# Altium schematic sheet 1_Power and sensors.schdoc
size 307 x 218 mm; Symbol: Drawing-Symbol_A4; Device: Drawing-Symbol_A4; @Project Name: Avian; @Page Count: 2; @Update Date: 2026-02-02; @Create Date: 2026-01-29; @Schematic Name: Avian_1; @Page No: 1; @Page Name: Power and sensors; Company: EasyEDA.com; Version: V1.0; Page Size: A4; @Create Time: 21:50:30; @Update Time: 22:16:31; Width: 1170; Height: 825; Region Start: 1; X Region Count: 6; Y Region Count: 4; Blade Width: 10; Title Block Position: 3; @Board Name: Avian_1
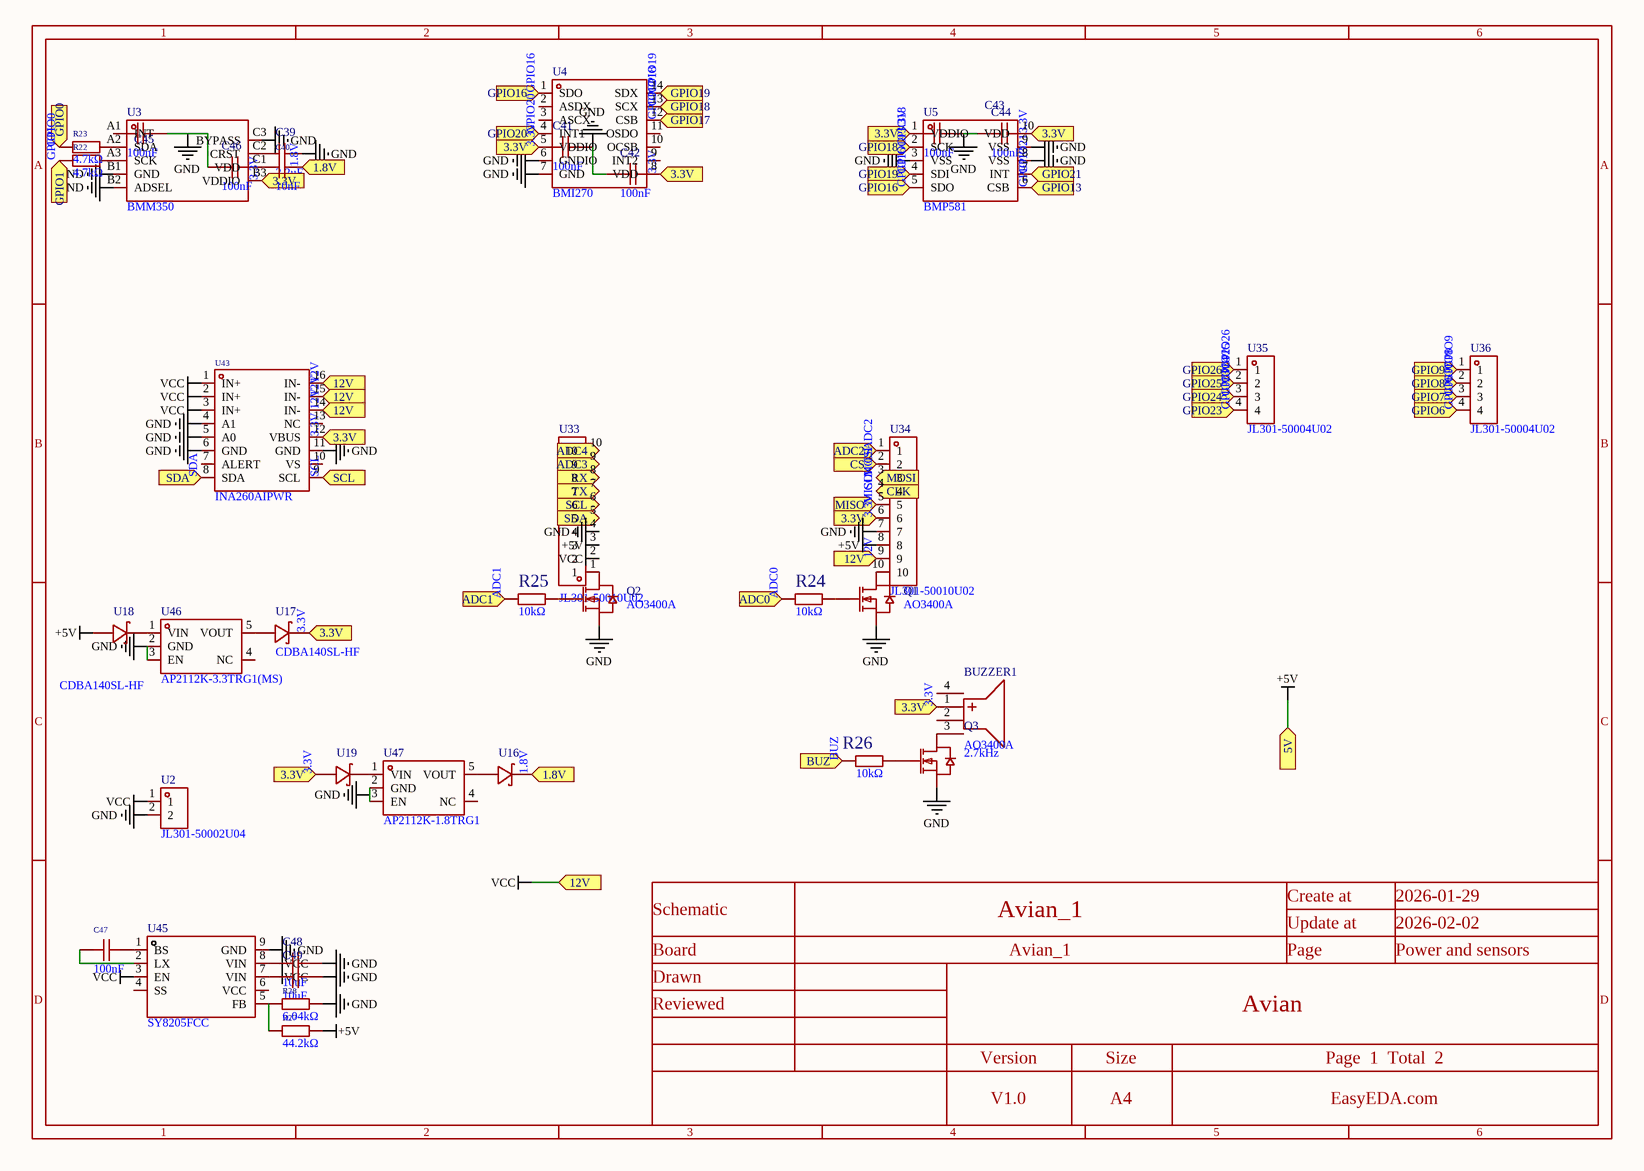
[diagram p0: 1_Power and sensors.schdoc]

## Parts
BUZZER1  2.7kHz  [BUZ-SMD_4P-L7.5-W7.5-P7.59-TL]
C39  2.2uF  [C1206]
C40  10nF  [C0603]
C41  100nF  [C0603]
C42  100nF  [C0603]
C43  100nF  [C0603]
C44  100nF  [C0603]
C45  100nF  [C0603]
C46  100nF  [C0603]
C47  100nF  [C0603]
C48  10uF  [C0805]
C49  10uF  [C0805]
Q1  AO3400A  [SOT-23-3_L2.9-W1.3-P1.90-LS2.4-BR]
Q2  AO3400A  [SOT-23-3_L2.9-W1.3-P1.90-LS2.4-BR]
Q3  AO3400A  [SOT-23-3_L2.9-W1.3-P1.90-LS2.4-BR]
R22  4.7kΩ  [R1206]
R23  4.7kΩ  [R1206]
R24  10kΩ  [R0603]
R25  10kΩ  [R0603]
R26  10kΩ  [R0603]
R27  44.2kΩ  [R0402]
R28  6.04kΩ  [R0402]
U2  JL301-50002U04  [CONN-TH_JL301-50002U01]
U3  BMM350  [WLCSP-9_L1.3-W1.3-R3-C3-P0.40-TL]
U4  BMI270  [LGA-14_L3.0-W2.5-P0.50-BR]
U5  BMP581  [LGA-10_L2.0-W2.0-P0.50-TL_BMP581]
U16  CDBA140SL-HF  [DO-214AC_L4.3-W2.7-LS5.3-RD]  (value not drawn)
U17  CDBA140SL-HF  [DO-214AC_L4.3-W2.7-LS5.3-RD]
U18  CDBA140SL-HF  [DO-214AC_L4.3-W2.7-LS5.3-RD]
U19  CDBA140SL-HF  [DO-214AC_L4.3-W2.7-LS5.3-RD]  (value not drawn)
U33  JL301-50010U02  [CONN-TH_10P-P5.00_JL301-50010U02]
U34  JL301-50010U02  [CONN-TH_10P-P5.00_JL301-50010U02]
U35  JL301-50004U02  [CONN-TH_4P-P5.00_JL301-50004U02]
U36  JL301-50004U02  [CONN-TH_4P-P5.00_JL301-50004U02]
U43  INA260AIPWR  [TSSOP-16_L5.0-W4.4-P0.65-LS6.4-BL-1]
U45  SY8205FCC  [SOIC-8_L5.0-W4.0-P1.27-LS6.0-BL-EP2.0]
U46  AP2112K-3.3TRG1(MS)  [SOT-23-5_L2.9-W1.6-P0.95-LS2.7-BR]
U47  AP2112K-1.8TRG1  [SOT-25_L3.0-W1.6-P0.95-LS2.8-BL]

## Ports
1.8V (in), 3.3V (in), 5V (in), 12V (in), ADC0 (in), ADC1 (in), ADC2 (in), ADC3 (in), ADC4 (in), BUZ (in), CLK (in), CS (in), GPIO0 (in), GPIO1 (in), GPIO6 (in), GPIO7 (in), GPIO8 (in), GPIO9 (in), GPIO13 (in), GPIO16 (in), GPIO17 (in), GPIO18 (in), GPIO19 (in), GPIO20 (in), GPIO21 (in), GPIO23 (in), GPIO24 (in), GPIO25 (in), GPIO26 (in), MISO (in), MOSI (in), RX (in), SCL (in), SDA (in), TX (in)

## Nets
12V: C48.1 C49.1 U2.1 U33.2 U34.9 U43.1(IN+) U43.2(IN+) U43.3(IN+) U43.14(IN-) U43.15(IN-) U43.16(IN-) U45.3(EN) U45.7(VIN) U45.8(VIN) ; port 12V  [also labelled VCC]
+5V: R27.2 U18.2 U33.3 U34.8 ; port 5V
GND: C39.2 C41.2 C42.1 C43.2 C44.1 C45.2 C46.1 C48.2 C49.2 Q1.2(S) Q2.2(S) Q3.2(S) R28.2 U2.2 U3.B1(GND) U3.B2(ADSEL) U3.C3(BYPASS) U4.6(GNDIO) U4.7(GND) U5.3(VSS) U5.8(VSS) U5.9(VSS) U33.4 U34.7 U43.4(A1) U43.5(A0) U43.6(GND) U43.11(GND) U45.9(GND) U46.2(GND) U46.3(EN) U47.2(GND) U47.3(EN)
1.8V: C40.2 U16.1 ; port 1.8V
3.3V: BUZZER1.1(+) C41.1 C42.2 C43.1 C44.2 U3.B3(VDDIO) U4.5(VDDIO) U4.8(VDD) U5.1(VDDIO) U5.10(VDD) U17.1 U19.2 U34.6 U43.12(VBUS) ; port 3.3V
ADC0: R24.1 ; port ADC0
ADC1: R25.1 ; port ADC1
ADC2: U34.1 ; port ADC2
ADC3: U33.9 ; port ADC3
ADC4: U33.10 ; port ADC4
BUZ: R26.1 ; port BUZ
CLK: U34.4 ; port CLK
CS: U34.2 ; port CS
GPIO0: R23.1 ; port GPIO0
GPIO1: R22.1 ; port GPIO1
GPIO6: U36.4 ; port GPIO6
GPIO7: U36.3 ; port GPIO7
GPIO8: U36.2 ; port GPIO8
GPIO9: U36.1 ; port GPIO9
GPIO13: U5.6(CSB) ; port GPIO13
GPIO16: U4.1(SDO) U5.5(SDO) ; port GPIO16
GPIO17: U4.12(CSB) ; port GPIO17
GPIO18: U4.13(SCX) U5.2(SCK) ; port GPIO18
GPIO19: U4.14(SDX) U5.4(SDI) ; port GPIO19
GPIO20: U4.4(INT1) ; port GPIO20
GPIO21: U5.7(INT) ; port GPIO21
GPIO23: U35.4 ; port GPIO23
GPIO24: U35.3 ; port GPIO24
GPIO25: U35.2 ; port GPIO25
GPIO26: U35.1 ; port GPIO26
MISO: U34.5 ; port MISO
MOSI: U34.3 ; port MOSI
RX: U33.8 ; port RX
SCL: U33.6 U43.9(SCL) ; port SCL
SDA: U33.5 U43.8(SDA) ; port SDA
TX: U33.7 ; port TX
NetBUZZER1_3: BUZZER1.3 Q3.3(D)
NetC39_1: C39.1 U3.C2(CRST)
NetC40_1: C40.1 C46.2 U3.C1(VDD)
NetC45_1: C45.1 U3.A1(INT)
NetC47_1: C47.1 U45.2(LX)
NetC47_2: C47.2 U45.1(BS)
NetQ1_1: Q1.1(G) R24.2
NetQ1_3: Q1.3(D) U34.10
NetQ2_1: Q2.1(G) R25.2
NetQ2_3: Q2.3(D) U33.1
NetQ3_1: Q3.1(G) R26.2
NetR22_2: R22.2 U3.A3(SCK)
NetR23_2: R23.2 U3.A2(SDA)
NetR27_1: R27.1 R28.1 U45.5(FB)
NetU16_2: U16.2 U47.5(VOUT)
NetU17_2: U17.2 U46.5(VOUT)
NetU18_1: U18.1 U46.1(VIN)
NetU19_1: U19.1 U47.1(VIN)

Not connected (* = marked no-connect by the designer): BUZZER1 2(-) 4; U4 2(ASDX) 3(ASCX) 9(INT2) 10(OCSB) 11(OSDO); U43 7(ALERT) 10(VS) 13(NC); U45 4(SS) 6(VCC); U46 4(NC); U47 4(NC)

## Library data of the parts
BUZZER1 = MLT-7525: Manufacturer: 华能; Add into BOM: yes; Driver Circuitry: Passive (Externally Driven); Voltage Rating: 3.6V; Voltage - Supply: 2.5V~4.5V; Current Consumption: 95mA; Sound Pressure Level(SPL): 80dB
C39 = CL31B225KBHNNNE: Manufacturer: SAMSUNG(三星); Add into BOM: yes; Tolerance: ±10%; Voltage Rating: 50V; Temperature Coefficient: X7R
C40 = CC0603KRX7R9BB103: Manufacturer: YAGEO(国巨); Add into BOM: yes; Tolerance: ±10%; Voltage Rating: 50V; Temperature Coefficient: X7R
C41-C46 = CC0603KRX7R9BB104: Manufacturer: YAGEO(国巨); Add into BOM: yes; Tolerance: ±10%; Voltage Rating: 50V; Temperature Coefficient: X7R
C47 = CL10B104KB8NNNC: Manufacturer: SAMSUNG(三星); Add into BOM: yes; Tolerance: ±10%; Voltage Rating: 50V; Temperature Coefficient: X7R
C48 C49 = CL21B106KOQNNNE: Manufacturer: SAMSUNG(三星); Add into BOM: yes; Tolerance: ±10%; Voltage Rating: 16V; Temperature Coefficient: X7R
Q1-Q3 = AO3400A_C20917: Manufacturer: AOS; Add into BOM: yes; Drain to Source Voltage: 30V; RDS(on): 48mΩ@2.5V; Gate Threshold Voltage (Vgs(th)): 1.45V@250uA; Gate Charge(Qg): 7nC@10V; Input Capacitance(Ciss): 630pF@15V; Type: N-Channel
R22 R23 = RMC12064.7K1%N: Manufacturer: Tyohm(幸亚电阻); Add into BOM: yes; Tolerance: ±1%; Power(Watts): 250mW; Voltage-Supply(Max): 200V; Temperature Coefficient: ±100ppm/℃
R24-R26 = 0603WAF1002T5E: Manufacturer: UNI-ROYAL(厚声); Add into BOM: yes; Tolerance: ±1%; Power(Watts): 100mW; Voltage-Supply(Max): 75V; Temperature Coefficient: ±100ppm/℃
R27 = RMC040244.2K1%N: Manufacturer: Tyohm(幸亚电阻); Add into BOM: yes; Tolerance: ±1%; Power(Watts): 62.5mW; Voltage-Supply(Max): 50V; Temperature Coefficient: ±100ppm/℃
R28 = RMC04026.04K1%N: Manufacturer: Tyohm(幸亚电阻); Add into BOM: yes; Tolerance: ±1%; Power(Watts): 62.5mW; Voltage-Supply(Max): 50V; Temperature Coefficient: ±100ppm/℃
U2 = JL301-50002U04: Manufacturer: JILN(锦凌); Add into BOM: yes; Number of Positions or Pins: 1x2P; Pitch: 5mm; Number of PINs Per Row: 2; Screw Specification: M2.5; Current Rating: 15A; Voltage Rating (Max): 300V; Wire Gauge - AWG: 12~24
U3 = BMM350_C17225907: Manufacturer: Bosch(博世); Add into BOM: yes
U4 = BMI270: Manufacturer: Bosch(博世); Add into BOM: yes; Sensor Type: 加速度计陀螺仪
U5 = BMP581: Manufacturer: Bosch(博世); Add into BOM: yes; Pressure range: 30Kpa~1.25bar; Voltage - Supply: 1.71V~3.6V; Standby Current: 1uA; Interface: I3C；SpI；I2C; Relative Accuracy: 6pa; Temperature Coefficient of Offset(TCO): 0.5pa/K
U16-U19 = CDBA140SL-HF: Manufacturer: Comchip(典琦); Add into BOM: yes; Diode Configuration: Independent Type; Forward Voltage (Vf@If): 270mV@1A; Reverse Voltage (Vr): 40V; Rectified Current: 1A; Reverse Leakage Current (Ir): 200uA@40V
U33 U34 = JL301-50010U02: Manufacturer: JILN(锦凌); Add into BOM: yes; Number of Positions or Pins: 1x10P; Pitch: 5mm; Number of PINs Per Row: 10; Screw Specification: M2.5; Current Rating: 15A; Voltage Rating (Max): 300V; Wire Gauge - AWG: 12~24
U35 U36 = JL301-50004U02: Manufacturer: JILN(锦凌); Add into BOM: yes; Number of Positions or Pins: 1x4P; Pitch: 5mm; Screw Specification: M2.5; Current Rating: 15A; Voltage Rating (Max): 300V; Wire Gauge - AWG: 12~24
U43 = INA260AIPWR: Manufacturer: TI(德州仪器); Add into BOM: yes
U45 = SY8205FCC: Manufacturer: Silergy(矽力杰); Add into BOM: yes; Function: Buck; Output Type: Adjustable; Voltage - Supply: 4.5V~30V; Output Current: 5A; Frequency - Switching: 500kHz; Number of Outputs: 1; Quiescent Current: 200uA; Switch tube (built-in/external): Built-in
U46 = AP2112K-3.3TRG1(MS): Manufacturer: MSKSEMI(美森科); Add into BOM: yes; Output Type: Fixed; Voltage - Supply: 6V; Output Voltage: 3.3V; Output Current: 600mA; Power Supply Rejection Ratio (PSRR): 75dB@(1kHz); standby current: 2uA; Output Configuration: Positive electrode; Number of Outputs: 1
U47 = AP2112K-1.8TRG1: Manufacturer: DIODES(美台); Add into BOM: yes; Output Type: Fixed; Voltage - Supply: 6V; Output Voltage: 1.8V; Output Current: 600mA; Power Supply Rejection Ratio (PSRR): 65dB@(1kHz); Voltage Dropout: 500mV@(600mA); standby current: 55uA; Noise: 50uVrms; Output Configuration: Positive; Number of Outputs: 1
